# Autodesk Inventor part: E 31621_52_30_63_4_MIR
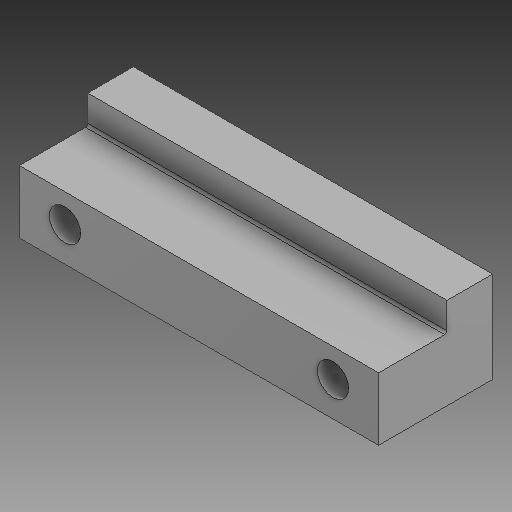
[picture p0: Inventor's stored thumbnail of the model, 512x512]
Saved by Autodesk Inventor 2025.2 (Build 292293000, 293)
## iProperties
Created: 2025-03
Part Number: E 31621_52_30_63_4_MIR
Material: Všeobecné
Document SubType Name: Modeling
Designer: Patrik
Mass: 14.8663 g
Surface Area: 57.9217 cm^2
Volume: 14.8663 cm^3
Density: 1 g/cm^3
Appearance: Výchozí
Author: Patrik
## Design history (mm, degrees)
derived "E 31621_52_30_63_4.ipt"
feature "Těleso1::E 31621_52_30_63_4.ipt" dims "d0" = 10
tag "Prvek štítků1"
node "Těleso1"
